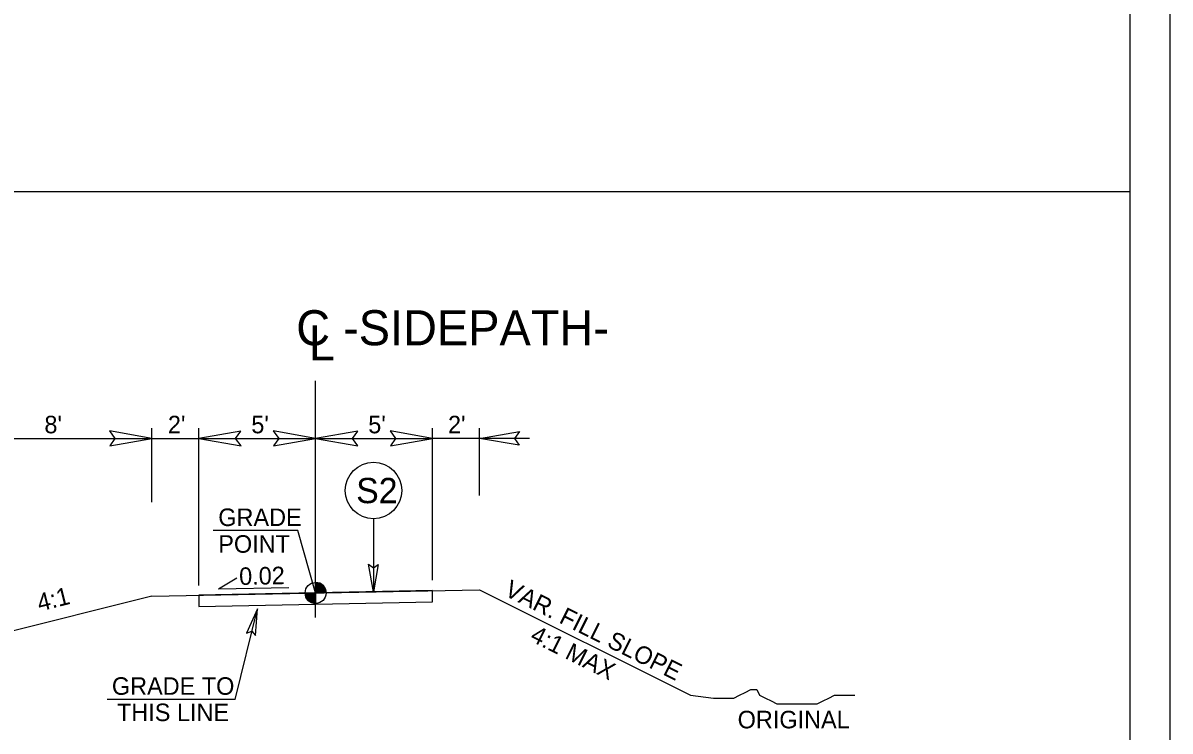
# Model space of a CAD drawing. Extents: x 1487909 to 1489267, y 497866 to 499814.
# Drawn here: x 1489002.61 to 1489051.66, y 497915.64 to 497945.93 of the extents above; entities that cross this region are included whole.
import ezdxf

# ---------------------------------------------------------------- set-up
doc = ezdxf.new("R2010")
doc.units = 0
for name, color, linetype in [('Prop Conc 4in Sidewalk', 7, 'Continuous'), ('Prop Dimension', 7, 'Continuous'), ('Prop Dimension Text', 7, 'Continuous'), ('Prop Shade Light', 7, 'Continuous'), ('Prop Terminator CELL', 7, 'Continuous'), ('Scratch_Level_1', 7, 'Continuous'), ('Sheet Plot Border Outside CELL', 7, 'Continuous'), ('Sheet Typical CELL', 7, 'Continuous'), ('Typical Grade Point Symbol CELL', 7, 'Continuous'), ('Typical Hinge Slope Arterial CELL', 7, 'Continuous'), ('Typical Hinge Slope Interstate CELL', 7, 'Continuous'), ('Typical ID Circle CELL', 7, 'Continuous'), ('Typical Pavement Slope CELL', 7, 'Continuous'), ('Typical Pavement Slope Information CELL', 7, 'Continuous'), ('Typical Terminator CELL', 7, 'Continuous'), ('Typical Text Grade Point CELL', 7, 'Continuous'), ('Typical Text ID Circle CELL', 7, 'Continuous')]:
    doc.layers.add(name, color=color, linetype=linetype)

msp = doc.modelspace()

# ---------------------------------------------------------------- linework, layer by layer
at = {"layer": 'Prop Conc 4in Sidewalk'}
for p, q in [((1489010.127, 497921.45), (1489020.127, 497921.65)), ((1489010.127, 497921.45), (1489010.127, 497920.968)), ((1489020.127, 497921.168), (1489020.127, 497921.65)), ((1489010.127, 497920.968), (1489020.127, 497921.168))]:
    msp.add_line(p, q, dxfattribs=at)
at = {"layer": 'Prop Dimension'}
for p, q in [((1489015.127, 497920.497), (1489015.127, 497930.618)), ((1489008.127, 497925.435), (1489008.127, 497928.598)), ((1489010.127, 497921.87), (1489010.127, 497928.598)), ((1489020.127, 497922.097), (1489020.127, 497928.598)), ((1489022.127, 497925.718), (1489022.127, 497928.598)), ((1489000.127, 497928.159), (1489008.127, 497928.159)), ((1489008.127, 497928.159), (1489010.127, 497928.159)), ((1489010.127, 497928.159), (1489015.127, 497928.159)), ((1489015.127, 497928.159), (1489020.127, 497928.159)), ((1489022.127, 497928.159), (1489020.127, 497928.159)), ((1489024.274, 497928.159), (1489022.127, 497928.159)), ((1489011.681, 497916.997), (1489012.641, 497920.875)), ((1489011.681, 497916.997), (1489006.208, 497916.997))]:
    msp.add_line(p, q, dxfattribs=at)
at = {"layer": 'Prop Dimension Text'}
for p, q in [((1489014.365, 497924.216), (1489010.75, 497924.216)), ((1489015.127, 497921.55), (1489014.365, 497924.216))]:
    msp.add_line(p, q, dxfattribs=at)
at = {"layer": 'Prop Shade Light'}
for p, q in [((1489020.127, 497921.65), (1489010.127, 497921.45)), ((1489010.127, 497921.45), (1489010.127, 497920.968)), ((1489020.127, 497921.168), (1489020.127, 497921.65)), ((1489010.127, 497920.968), (1489020.127, 497921.168))]:
    msp.add_line(p, q, dxfattribs=at)
at = {"layer": 'Prop Terminator CELL'}
for points in [[(1489006.327, 497927.849), (1489008.127, 497928.159), (1489006.317, 497928.479), (1489006.547, 497928.159)], [(1489011.927, 497928.469), (1489010.127, 497928.159), (1489011.937, 497927.839), (1489011.707, 497928.159)], [(1489013.327, 497927.849), (1489015.127, 497928.159), (1489013.317, 497928.479), (1489013.547, 497928.159)], [(1489016.927, 497928.469), (1489015.127, 497928.159), (1489016.937, 497927.839), (1489016.707, 497928.159)], [(1489018.327, 497927.849), (1489020.127, 497928.159), (1489018.317, 497928.479), (1489018.547, 497928.159)], [(1489023.837, 497927.865), (1489022.127, 497928.159), (1489023.846, 497928.463), (1489023.628, 497928.159)], [(1489012.559, 497919.736), (1489012.641, 497920.875), (1489012.175, 497919.825), (1489012.404, 497919.916)]]:
    msp.add_lwpolyline(points, close=True, dxfattribs=at)
at = {"layer": 'Scratch_Level_1'}
msp.add_line((1488899.964, 497938.721), (1489049.964, 497938.721), dxfattribs=at)
at = {"layer": 'Sheet Plot Border Outside CELL'}
msp.add_lwpolyline([(1489051.664, 497976.221), (1488883.264, 497976.221), (1488883.264, 497866.221), (1489051.664, 497866.221)], close=True, dxfattribs=at)
at = {"layer": 'Sheet Typical CELL'}
msp.add_lwpolyline([(1489049.964, 497973.721), (1488899.964, 497973.721), (1488899.964, 497868.721), (1489049.964, 497868.721)], close=True, dxfattribs=at)
at = {"layer": 'Typical Grade Point Symbol CELL'}
for p, q in [((1489015.127, 497921.55), (1489015.127, 497921.997)), ((1489015.127, 497921.55), (1489015.127, 497921.997)), ((1489014.679, 497921.55), (1489015.127, 497921.55)), ((1489014.679, 497921.55), (1489015.127, 497921.55)), ((1489015.126, 497921.102), (1489015.127, 497921.55)), ((1489015.127, 497921.55), (1489015.126, 497921.102)), ((1489015.126, 497921.102), (1489015.127, 497921.55)), ((1489015.127, 497921.55), (1489015.126, 497921.102)), ((1489015.574, 497921.55), (1489015.127, 497921.55)), ((1489015.574, 497921.55), (1489015.127, 497921.55))]:
    msp.add_line(p, q, dxfattribs=at)
for points in [[(1489015.131, 497921.997), (1489015.131, 497921.997), (1489015.131, 497921.55)], [(1489015.131, 497921.997), (1489015.131, 497921.997), (1489015.131, 497921.55)], [(1489015.14, 497921.997), (1489015.14, 497921.55)], [(1489015.14, 497921.997), (1489015.14, 497921.55)], [(1489015.149, 497921.996), (1489015.149, 497921.55)], [(1489015.149, 497921.996), (1489015.149, 497921.55)], [(1489015.158, 497921.996), (1489015.158, 497921.55)], [(1489015.158, 497921.996), (1489015.158, 497921.55)], [(1489015.167, 497921.995), (1489015.167, 497921.55)], [(1489015.167, 497921.995), (1489015.167, 497921.55)], [(1489015.176, 497921.994), (1489015.176, 497921.55)], [(1489015.176, 497921.994), (1489015.176, 497921.55)], [(1489015.185, 497921.993), (1489015.185, 497921.55)], [(1489015.185, 497921.993), (1489015.185, 497921.55)], [(1489015.193, 497921.992), (1489015.193, 497921.55)], [(1489015.193, 497921.992), (1489015.193, 497921.55)], [(1489015.202, 497921.991), (1489015.202, 497921.55)], [(1489015.202, 497921.991), (1489015.202, 497921.55)], [(1489015.211, 497921.989), (1489015.211, 497921.55)], [(1489015.211, 497921.989), (1489015.211, 497921.55)], [(1489015.22, 497921.987), (1489015.22, 497921.55)], [(1489015.22, 497921.987), (1489015.22, 497921.55)], [(1489015.229, 497921.985), (1489015.229, 497921.55)], [(1489015.229, 497921.985), (1489015.229, 497921.55)], [(1489015.238, 497921.983), (1489015.238, 497921.55)], [(1489015.238, 497921.983), (1489015.238, 497921.55)], [(1489015.247, 497921.98), (1489015.247, 497921.55)], [(1489015.247, 497921.98), (1489015.247, 497921.55)], [(1489015.256, 497921.978), (1489015.256, 497921.55)], [(1489015.256, 497921.978), (1489015.256, 497921.55)], [(1489015.265, 497921.975), (1489015.265, 497921.55)], [(1489015.265, 497921.975), (1489015.265, 497921.55)], [(1489015.274, 497921.972), (1489015.274, 497921.55)], [(1489015.274, 497921.972), (1489015.274, 497921.55)], [(1489015.283, 497921.969), (1489015.283, 497921.55)], [(1489015.283, 497921.969), (1489015.283, 497921.55)], [(1489015.292, 497921.965), (1489015.292, 497921.55)], [(1489015.292, 497921.965), (1489015.292, 497921.55)], [(1489015.301, 497921.961), (1489015.301, 497921.55)], [(1489015.301, 497921.961), (1489015.301, 497921.55)], [(1489015.31, 497921.957), (1489015.31, 497921.55)], [(1489015.31, 497921.957), (1489015.31, 497921.55)], [(1489015.319, 497921.953), (1489015.319, 497921.55)], [(1489015.319, 497921.953), (1489015.319, 497921.55)], [(1489015.328, 497921.949), (1489015.328, 497921.55)], [(1489015.328, 497921.949), (1489015.328, 497921.55)], [(1489015.337, 497921.944), (1489015.337, 497921.55)], [(1489015.337, 497921.944), (1489015.337, 497921.55)], [(1489015.346, 497921.94), (1489015.346, 497921.55)], [(1489015.346, 497921.94), (1489015.346, 497921.55)], [(1489015.355, 497921.935), (1489015.355, 497921.55)], [(1489015.355, 497921.935), (1489015.355, 497921.55)], [(1489015.364, 497921.93), (1489015.364, 497921.55)], [(1489015.364, 497921.93), (1489015.364, 497921.55)], [(1489015.373, 497921.924), (1489015.373, 497921.55)], [(1489015.373, 497921.924), (1489015.373, 497921.55)], [(1489015.381, 497921.918), (1489015.381, 497921.55)], [(1489015.381, 497921.918), (1489015.381, 497921.55)], [(1489015.39, 497921.911), (1489015.39, 497921.55)], [(1489015.39, 497921.911), (1489015.39, 497921.55)], [(1489015.399, 497921.905), (1489015.399, 497921.55)], [(1489015.399, 497921.905), (1489015.399, 497921.55)], [(1489015.408, 497921.898), (1489015.408, 497921.55)], [(1489015.408, 497921.898), (1489015.408, 497921.55)], [(1489015.417, 497921.89), (1489015.417, 497921.55)], [(1489015.417, 497921.89), (1489015.417, 497921.55)], [(1489015.426, 497921.882), (1489015.426, 497921.55)], [(1489015.426, 497921.882), (1489015.426, 497921.55)], [(1489015.435, 497921.874), (1489015.435, 497921.55)], [(1489015.435, 497921.874), (1489015.435, 497921.55)], [(1489015.444, 497921.865), (1489015.444, 497921.55)], [(1489015.444, 497921.865), (1489015.444, 497921.55)], [(1489015.453, 497921.856), (1489015.453, 497921.55)], [(1489015.453, 497921.856), (1489015.453, 497921.55)], [(1489015.462, 497921.846), (1489015.462, 497921.55)], [(1489015.462, 497921.846), (1489015.462, 497921.55)], [(1489015.471, 497921.835), (1489015.471, 497921.55)], [(1489015.471, 497921.835), (1489015.471, 497921.55)], [(1489015.48, 497921.824), (1489015.48, 497921.55)], [(1489015.48, 497921.824), (1489015.48, 497921.55)], [(1489015.489, 497921.812), (1489015.489, 497921.55)], [(1489015.489, 497921.812), (1489015.489, 497921.55)], [(1489015.498, 497921.799), (1489015.498, 497921.55)], [(1489015.498, 497921.799), (1489015.498, 497921.55)], [(1489015.507, 497921.785), (1489015.507, 497921.55)], [(1489015.507, 497921.785), (1489015.507, 497921.55)], [(1489015.516, 497921.77), (1489015.516, 497921.55)], [(1489015.516, 497921.77), (1489015.516, 497921.55)], [(1489015.525, 497921.754), (1489015.525, 497921.55)], [(1489015.525, 497921.754), (1489015.525, 497921.55)], [(1489015.534, 497921.736), (1489015.534, 497921.55)], [(1489015.534, 497921.736), (1489015.534, 497921.55)], [(1489015.543, 497921.715), (1489015.543, 497921.55)], [(1489015.543, 497921.715), (1489015.543, 497921.55)], [(1489014.681, 497921.55), (1489014.681, 497921.501)], [(1489014.681, 497921.55), (1489014.681, 497921.501)], [(1489014.69, 497921.55), (1489014.69, 497921.448)], [(1489014.69, 497921.55), (1489014.69, 497921.448)], [(1489014.699, 497921.55), (1489014.699, 497921.416)], [(1489014.699, 497921.55), (1489014.699, 497921.416)], [(1489014.708, 497921.55), (1489014.708, 497921.389)], [(1489014.708, 497921.55), (1489014.708, 497921.389)], [(1489014.717, 497921.55), (1489014.717, 497921.369)], [(1489014.717, 497921.55), (1489014.717, 497921.369)], [(1489014.726, 497921.55), (1489014.726, 497921.35)], [(1489014.726, 497921.55), (1489014.726, 497921.35)], [(1489014.735, 497921.55), (1489014.735, 497921.333)], [(1489014.735, 497921.55), (1489014.735, 497921.333)], [(1489014.744, 497921.55), (1489014.744, 497921.317)], [(1489014.744, 497921.55), (1489014.744, 497921.317)], [(1489014.753, 497921.55), (1489014.753, 497921.303)], [(1489014.753, 497921.55), (1489014.753, 497921.303)], [(1489014.762, 497921.55), (1489014.762, 497921.29)], [(1489014.762, 497921.55), (1489014.762, 497921.29)], [(1489014.771, 497921.55), (1489014.771, 497921.278)], [(1489014.771, 497921.55), (1489014.771, 497921.278)], [(1489014.78, 497921.55), (1489014.78, 497921.267)], [(1489014.78, 497921.55), (1489014.78, 497921.267)], [(1489014.789, 497921.55), (1489014.789, 497921.256)], [(1489014.789, 497921.55), (1489014.789, 497921.256)], [(1489014.798, 497921.55), (1489014.798, 497921.246)], [(1489014.798, 497921.55), (1489014.798, 497921.246)], [(1489014.807, 497921.55), (1489014.807, 497921.236)], [(1489014.807, 497921.55), (1489014.807, 497921.236)], [(1489014.816, 497921.55), (1489014.816, 497921.227)], [(1489014.816, 497921.55), (1489014.816, 497921.227)], [(1489014.824, 497921.55), (1489014.824, 497921.219)], [(1489014.824, 497921.55), (1489014.824, 497921.219)], [(1489014.833, 497921.55), (1489014.833, 497921.211)], [(1489014.833, 497921.55), (1489014.833, 497921.211)], [(1489014.842, 497921.55), (1489014.842, 497921.203)], [(1489014.842, 497921.55), (1489014.842, 497921.203)], [(1489014.851, 497921.55), (1489014.851, 497921.197)], [(1489014.851, 497921.55), (1489014.851, 497921.197)], [(1489014.86, 497921.55), (1489014.86, 497921.19)], [(1489014.86, 497921.55), (1489014.86, 497921.19)], [(1489014.869, 497921.55), (1489014.869, 497921.184)], [(1489014.869, 497921.55), (1489014.869, 497921.184)], [(1489014.878, 497921.55), (1489014.878, 497921.178)], [(1489014.878, 497921.55), (1489014.878, 497921.178)], [(1489014.887, 497921.55), (1489014.887, 497921.172)], [(1489014.887, 497921.55), (1489014.887, 497921.172)], [(1489014.896, 497921.55), (1489014.896, 497921.166)], [(1489014.896, 497921.55), (1489014.896, 497921.166)], [(1489014.905, 497921.55), (1489014.905, 497921.161)], [(1489014.905, 497921.55), (1489014.905, 497921.161)], [(1489014.914, 497921.55), (1489014.914, 497921.156)], [(1489014.914, 497921.55), (1489014.914, 497921.156)], [(1489014.923, 497921.55), (1489014.923, 497921.151)], [(1489014.923, 497921.55), (1489014.923, 497921.151)], [(1489014.932, 497921.55), (1489014.932, 497921.147)], [(1489014.932, 497921.55), (1489014.932, 497921.147)], [(1489014.941, 497921.55), (1489014.941, 497921.143)], [(1489014.941, 497921.55), (1489014.941, 497921.143)], [(1489014.95, 497921.55), (1489014.95, 497921.139)], [(1489014.95, 497921.55), (1489014.95, 497921.139)], [(1489014.959, 497921.55), (1489014.959, 497921.135)], [(1489014.959, 497921.55), (1489014.959, 497921.135)], [(1489014.968, 497921.55), (1489014.968, 497921.131)], [(1489014.968, 497921.55), (1489014.968, 497921.131)], [(1489014.977, 497921.55), (1489014.977, 497921.128)], [(1489014.977, 497921.55), (1489014.977, 497921.128)], [(1489014.986, 497921.55), (1489014.986, 497921.125)], [(1489014.986, 497921.55), (1489014.986, 497921.125)], [(1489014.995, 497921.55), (1489014.995, 497921.122)], [(1489014.995, 497921.55), (1489014.995, 497921.122)], [(1489015.004, 497921.55), (1489015.004, 497921.12)], [(1489015.004, 497921.55), (1489015.004, 497921.12)], [(1489015.012, 497921.55), (1489015.012, 497921.117)], [(1489015.012, 497921.55), (1489015.012, 497921.117)], [(1489015.021, 497921.55), (1489015.021, 497921.115)], [(1489015.021, 497921.55), (1489015.021, 497921.115)], [(1489015.03, 497921.55), (1489015.03, 497921.113)], [(1489015.03, 497921.55), (1489015.03, 497921.113)], [(1489015.039, 497921.55), (1489015.039, 497921.111)], [(1489015.039, 497921.55), (1489015.039, 497921.111)], [(1489015.048, 497921.55), (1489015.048, 497921.109)], [(1489015.048, 497921.55), (1489015.048, 497921.109)], [(1489015.057, 497921.55), (1489015.057, 497921.108)], [(1489015.057, 497921.55), (1489015.057, 497921.108)], [(1489015.066, 497921.55), (1489015.066, 497921.106)], [(1489015.066, 497921.55), (1489015.066, 497921.106)], [(1489015.075, 497921.55), (1489015.075, 497921.105)], [(1489015.075, 497921.55), (1489015.075, 497921.105)], [(1489015.084, 497921.55), (1489015.084, 497921.104)], [(1489015.084, 497921.55), (1489015.084, 497921.104)], [(1489015.093, 497921.55), (1489015.093, 497921.103)], [(1489015.093, 497921.55), (1489015.093, 497921.103)], [(1489015.102, 497921.55), (1489015.102, 497921.103)], [(1489015.102, 497921.55), (1489015.102, 497921.103)], [(1489015.111, 497921.55), (1489015.111, 497921.102)], [(1489015.111, 497921.55), (1489015.111, 497921.102)], [(1489015.12, 497921.55), (1489015.12, 497921.102), (1489015.12, 497921.102)], [(1489015.12, 497921.55), (1489015.12, 497921.102), (1489015.12, 497921.102)], [(1489015.552, 497921.69), (1489015.552, 497921.55)], [(1489015.552, 497921.69), (1489015.552, 497921.55)], [(1489015.561, 497921.659), (1489015.561, 497921.55)], [(1489015.561, 497921.659), (1489015.561, 497921.55)], [(1489015.569, 497921.613), (1489015.569, 497921.55)], [(1489015.569, 497921.613), (1489015.569, 497921.55)]]:
    msp.add_lwpolyline(points, dxfattribs=at)
msp.add_circle((1489015.126, 497921.55), 0.448, dxfattribs=at)
msp.add_circle((1489015.126, 497921.55), 0.448, dxfattribs=at)
for start, end in [(359.9905, 89.9905), (359.9905, 89.9905), (179.9905, 269.9905), (179.9905, 269.9905)]:
    msp.add_arc((1489015.126, 497921.55), 0.448, start, end, dxfattribs=at)
at = {"layer": 'Typical Hinge Slope Arterial CELL'}
for p, q in [((1489008.127, 497921.41), (1489000.127, 497919.41)), ((1489022.127, 497921.69), (1489031.156, 497917.175))]:
    msp.add_line(p, q, dxfattribs=at)
msp.add_lwpolyline([(1489031.156, 497917.175), (1489032.141, 497917.052), (1489032.388, 497917.052), (1489032.758, 497917.052), (1489033.004, 497917.052), (1489033.251, 497917.175), (1489033.497, 497917.299), (1489033.743, 497917.422), (1489033.99, 497917.422), (1489034.113, 497917.175), (1489034.36, 497917.052), (1489034.606, 497916.929), (1489034.852, 497916.806), (1489035.099, 497916.806), (1489035.345, 497916.806), (1489035.592, 497916.806), (1489035.838, 497916.806), (1489036.084, 497916.806), (1489036.331, 497916.806), (1489036.577, 497916.806), (1489036.823, 497916.929), (1489037.07, 497917.052), (1489037.316, 497917.175), (1489037.686, 497917.175), (1489037.933, 497917.175), (1489038.179, 497917.175)], dxfattribs=at)
at = {"layer": 'Typical ID Circle CELL'}
msp.add_line((1489017.603, 497924.722), (1489017.603, 497921.599), dxfattribs=at)
msp.add_circle((1489017.603, 497925.931), 1.208, dxfattribs=at)
at = {"layer": 'Typical Pavement Slope CELL'}
msp.add_line((1489008.127, 497921.41), (1489022.127, 497921.69), dxfattribs=at)
at = {"layer": 'Typical Pavement Slope Information CELL'}
for q in [(1489011.758, 497922.202), (1489013.981, 497921.789)]:
    msp.add_line((1489010.975, 497921.729), q, dxfattribs=at)
at = {"layer": 'Typical Terminator CELL'}
msp.add_lwpolyline([(1489017.805, 497922.771), (1489017.603, 497921.599), (1489017.394, 497922.777), (1489017.603, 497922.628)], close=True, dxfattribs=at)
msp.add_lwpolyline([(1489017.805, 497922.771), (1489017.603, 497921.599), (1489017.394, 497922.777), (1489017.603, 497922.628)], close=True, dxfattribs=at)

# ---------------------------------------------------------------- texts
at = {"layer": 'Prop Dimension Text'}
for s, p in [("8'", (1489003.529, 497928.379)), ("2'", (1489008.81, 497928.379)), ("5'", (1489012.377, 497928.379)), ("5'", (1489017.377, 497928.379)), ("2'", (1489020.788, 497928.379)), ('GRADE TO', (1489006.414, 497917.193)), ('THIS LINE', (1489006.632, 497916.068))]:
    msp.add_text(s, height=0.75, dxfattribs=at).set_placement(p)
at = {"layer": 'Typical Hinge Slope Arterial CELL'}
for s, rotation, p in [('4:1', 14.0362, (1489003.322, 497920.752)), ('VAR. FILL SLOPE', 333.4658, (1489023.152, 497921.466)), ('4:1 MAX', 333.4658, (1489024.25, 497919.521))]:
    msp.add_text(s, height=0.75, rotation=rotation, dxfattribs=at).set_placement(p)
msp.add_text('ORIGINAL', height=0.75, dxfattribs=at).set_placement((1489033.173, 497915.759))
at = {"layer": 'Typical Hinge Slope Interstate CELL'}
for s, p in [('C -SIDEPATH-', (1489014.296, 497932.144)), ('L', (1489014.837, 497931.496))]:
    msp.add_text(s, height=1.5, dxfattribs=at).set_placement(p)
at = {"layer": 'Typical Pavement Slope Information CELL'}
msp.add_text('0.02', height=0.75, rotation=1.1457, dxfattribs=at).set_placement((1489011.864, 497921.889))
at = {"layer": 'Typical Text Grade Point CELL'}
for s, p in [('GRADE', (1489010.964, 497924.412)), ('POINT', (1489010.964, 497923.27))]:
    msp.add_text(s, height=0.75, dxfattribs=at).set_placement(p)
at = {"layer": 'Typical Text ID Circle CELL'}
msp.add_text('S2', height=1.0817, dxfattribs=at).set_placement((1489016.861, 497925.39))

doc.saveas('drawing.dxf')
